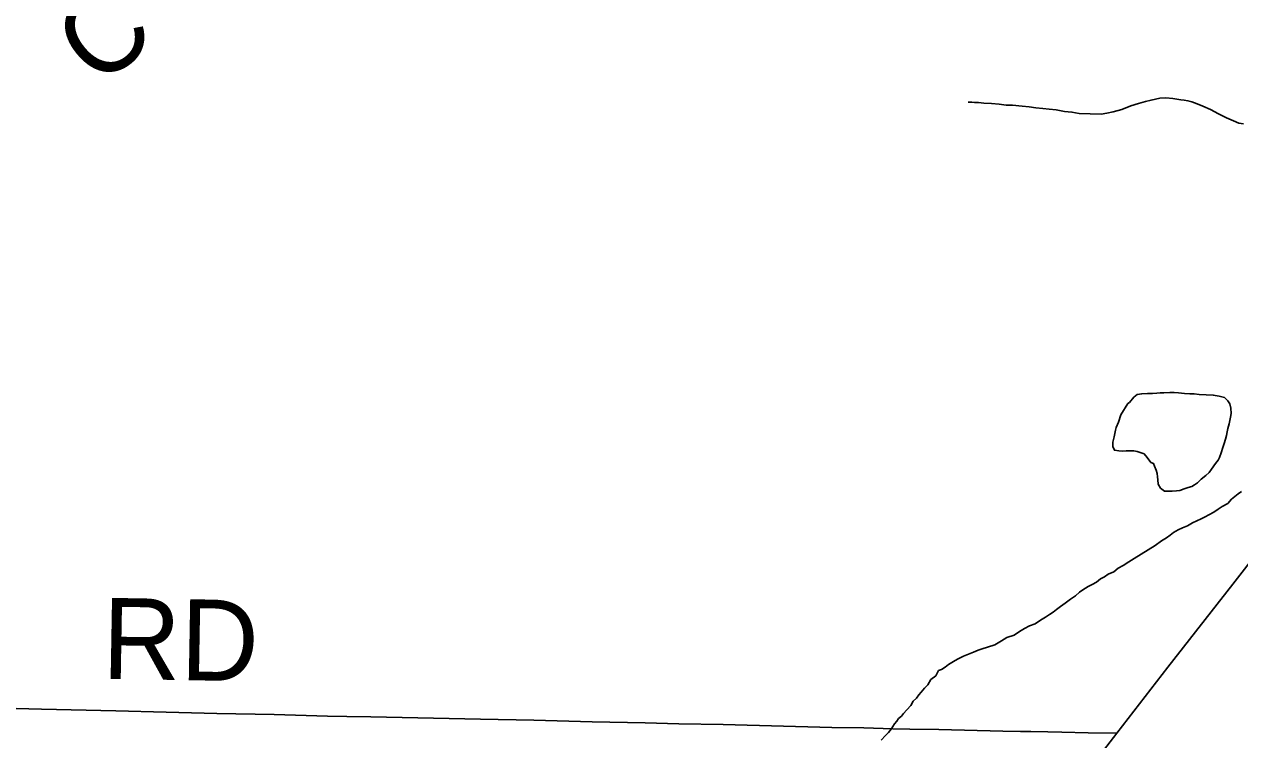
# Model space of a CAD drawing. Extents: x 0 to 34, y 0 to 22.
# Drawn here: x 24.806 to 25.659, y 15.392 to 15.894 of the extents above; entities that cross this region are included whole.
import ezdxf

# ---------------------------------------------------------------- set-up
doc = ezdxf.new("R2010")
doc.units = 0
for name, color, linetype in [('GM_X_County_Road_Text', 7, 'Continuous'), ('GM_X_Minor_Lake', 7, 'Continuous'), ('GM_X_Minor_River', 7, 'Continuous'), ('GM_X_State_Route', 7, 'Continuous'), ('GM_X_Township_Road', 7, 'Continuous'), ('GM_X_Township_Road_Text', 7, 'Continuous')]:
    doc.layers.add(name, color=color, linetype=linetype)

msp = doc.modelspace()

# ---------------------------------------------------------------- linework, layer by layer
at = {"layer": 'GM_X_Minor_Lake'}
for points in [[(25.58092, 15.62812), (25.5761, 15.62029), (25.57441, 15.61502), (25.57276, 15.61127), (25.57232, 15.60938), (25.57187, 15.60712), (25.57142, 15.60485), (25.57053, 15.60107), (25.57044, 15.59803), (25.57149, 15.59533), (25.57452, 15.59485), (25.57719, 15.59477), (25.57986, 15.59506), (25.58253, 15.59497), (25.58519, 15.59488), (25.58746, 15.59442), (25.59236, 15.59274), (25.59457, 15.59039), (25.59712, 15.58688), (25.599, 15.58606), (25.5997, 15.58413), (25.60075, 15.58143), (25.60144, 15.57913), (25.60175, 15.57683), (25.60206, 15.57454), (25.60234, 15.57148), (25.60378, 15.56877), (25.60676, 15.56677), (25.61209, 15.5666), (25.61514, 15.56688), (25.61744, 15.56718), (25.62052, 15.56822), (25.62322, 15.56927), (25.62591, 15.56995), (25.62784, 15.57102), (25.62979, 15.57248), (25.63254, 15.57506), (25.63567, 15.57761), (25.63803, 15.57982), (25.63962, 15.58205), (25.64242, 15.58614), (25.64439, 15.58836), (25.64521, 15.59023), (25.64646, 15.59362), (25.64773, 15.59738), (25.64857, 15.60002), (25.64943, 15.60303), (25.65028, 15.60567), (25.65074, 15.60831), (25.6512, 15.61058), (25.65207, 15.61398), (25.65252, 15.61625), (25.65297, 15.61852), (25.65344, 15.62116), (25.65318, 15.62498), (25.65251, 15.62804), (25.65105, 15.62999), (25.64884, 15.63235), (25.64507, 15.63323), (25.6409, 15.63413), (25.63596, 15.63429), (25.63101, 15.63446), (25.6276, 15.63495), (25.62456, 15.63505), (25.62075, 15.63518), (25.61658, 15.6357), (25.61353, 15.6358), (25.61049, 15.6359), (25.6063, 15.63566), (25.60363, 15.63574), (25.60134, 15.63544), (25.59828, 15.63516), (25.59486, 15.63527), (25.59066, 15.63503), (25.58759, 15.63437), (25.58525, 15.63255), (25.58208, 15.62884), (25.58092, 15.62812)], [(25.63803, 15.57982), (25.63962, 15.58205), (25.64242, 15.58614), (25.64439, 15.58836), (25.64521, 15.59023), (25.64646, 15.59362), (25.64773, 15.59738), (25.64857, 15.60002), (25.64943, 15.60303), (25.65028, 15.60567), (25.65074, 15.60831), (25.6512, 15.61058), (25.65207, 15.61398), (25.65252, 15.61625), (25.65297, 15.61852), (25.65344, 15.62116), (25.65318, 15.62498), (25.65251, 15.62804), (25.65105, 15.62999), (25.64884, 15.63235), (25.64507, 15.63323), (25.6409, 15.63413), (25.63596, 15.63429), (25.63101, 15.63446), (25.6276, 15.63495), (25.62456, 15.63505), (25.62075, 15.63518), (25.61658, 15.6357), (25.61353, 15.6358), (25.61049, 15.6359), (25.6063, 15.63566), (25.60363, 15.63574), (25.60134, 15.63544), (25.59828, 15.63516), (25.59486, 15.63527), (25.59066, 15.63503), (25.58759, 15.63437), (25.58525, 15.63255), (25.58208, 15.62884), (25.58092, 15.62812)], [(25.58092, 15.62812), (25.5761, 15.62029), (25.57441, 15.61502), (25.57276, 15.61127), (25.57232, 15.60938), (25.57187, 15.60712), (25.57142, 15.60485), (25.57053, 15.60107), (25.57044, 15.59803), (25.57149, 15.59533), (25.57452, 15.59485), (25.57719, 15.59477), (25.57986, 15.59506), (25.58253, 15.59497), (25.58519, 15.59488), (25.58746, 15.59442), (25.59236, 15.59274), (25.59457, 15.59039), (25.59712, 15.58688), (25.599, 15.58606), (25.5997, 15.58413), (25.60075, 15.58143), (25.60144, 15.57913), (25.60175, 15.57683), (25.60206, 15.57454), (25.60234, 15.57148), (25.60378, 15.56877), (25.60676, 15.56677), (25.61209, 15.5666), (25.61514, 15.56688), (25.61744, 15.56718), (25.62052, 15.56822), (25.62322, 15.56927), (25.62591, 15.56995), (25.62784, 15.57102), (25.62979, 15.57248), (25.63254, 15.57506), (25.63567, 15.57761), (25.63803, 15.57982)]]:
    msp.add_lwpolyline(points, dxfattribs=at)
at = {"layer": 'GM_X_Minor_River'}
for points in [[(25.66221, 15.82442), (25.6588, 15.82492), (25.65505, 15.82656), (25.65016, 15.82863), (25.64454, 15.83148), (25.63892, 15.83432), (25.63366, 15.83678), (25.62953, 15.83844), (25.62576, 15.8397), (25.62312, 15.84055), (25.62047, 15.84102), (25.61819, 15.8411), (25.6125, 15.84205), (25.60757, 15.84259), (25.60337, 15.84235), (25.60031, 15.84169), (25.59724, 15.84103), (25.5934, 15.84001), (25.5884, 15.83866), (25.58302, 15.83693), (25.57684, 15.83447), (25.5707, 15.83277), (25.56609, 15.83178), (25.56227, 15.83115), (25.54667, 15.83166), (25.54175, 15.83259), (25.53643, 15.83314), (25.53075, 15.83409), (25.52582, 15.83463), (25.52126, 15.83517), (25.51633, 15.83571), (25.51178, 15.83624), (25.50684, 15.83678), (25.5, 15.83739), (25.49544, 15.83754), (25.49051, 15.83808), (25.48519, 15.83864), (25.47987, 15.83881), (25.47607, 15.83932), (25.47341, 15.83941), (25.47151, 15.83947), (25.46923, 15.83955), (25.46885, 15.83956)], [(25.66083, 15.56651), (25.65849, 15.56469), (25.65615, 15.56286), (25.6538, 15.56104), (25.65104, 15.55808), (25.64716, 15.55593), (25.64444, 15.55412), (25.64133, 15.55194), (25.63784, 15.55015), (25.63513, 15.54872), (25.63242, 15.54728), (25.62932, 15.54587), (25.62623, 15.54445), (25.62274, 15.54228), (25.61926, 15.54087), (25.61617, 15.53945), (25.61307, 15.53765), (25.61072, 15.53583), (25.608, 15.53401), (25.6045, 15.53185), (25.60021, 15.52856), (25.58545, 15.51954), (25.58156, 15.51701), (25.57767, 15.51447), (25.57418, 15.51268), (25.57106, 15.51012), (25.56719, 15.50835), (25.56447, 15.50654), (25.56176, 15.5051), (25.55902, 15.50291), (25.55592, 15.50111), (25.55321, 15.49968), (25.55127, 15.4986), (25.54933, 15.49752), (25.54698, 15.4957), (25.54424, 15.49313), (25.54074, 15.49096), (25.53684, 15.48804), (25.53372, 15.48586), (25.53098, 15.48367), (25.52864, 15.48185), (25.52592, 15.48003), (25.52319, 15.47822), (25.5197, 15.47606), (25.51581, 15.47352), (25.51195, 15.47213), (25.50847, 15.47034), (25.50497, 15.46817), (25.50108, 15.46564), (25.49608, 15.4639), (25.4922, 15.46174), (25.48754, 15.45885), (25.48253, 15.45712), (25.47869, 15.4561), (25.47599, 15.45505), (25.47252, 15.45364), (25.46905, 15.45224), (25.46557, 15.45083), (25.46325, 15.44976), (25.46132, 15.44869), (25.4586, 15.44725), (25.45511, 15.44509), (25.45276, 15.44326), (25.45004, 15.44145), (25.44811, 15.44075), (25.44609, 15.43701), (25.44258, 15.43447), (25.44056, 15.43073), (25.4382, 15.42852), (25.43582, 15.42556), (25.43424, 15.42371), (25.43264, 15.42148), (25.43029, 15.41927), (25.42867, 15.41628), (25.42591, 15.41333), (25.42354, 15.41075), (25.42196, 15.4089), (25.42, 15.40706), (25.41879, 15.4052), (25.41721, 15.40334), (25.41481, 15.39962), (25.41283, 15.3974), (25.41086, 15.39519), (25.40771, 15.39187)]]:
    msp.add_lwpolyline(points, dxfattribs=at)
at = {"layer": 'GM_X_State_Route'}
for points in [[(25.57313, 15.39691), (25.60896, 15.44324), (25.65464, 15.50143), (25.692, 15.54957), (25.70849, 15.57059), (25.71659, 15.58157), (25.7215, 15.58872), (25.72606, 15.59607), (25.7311, 15.6053), (25.73479, 15.61311), (25.73734, 15.61941), (25.73956, 15.62581), (25.74175, 15.63353), (25.74395, 15.64381), (25.7462, 15.65726), (25.75078, 15.69114), (25.75665, 15.73489), (25.76276, 15.78237), (25.76637, 15.81075), (25.77336, 15.86), (25.77686, 15.88586), (25.78049, 15.91483)], [(25.55046, 15.36744), (25.57313, 15.39691)]]:
    msp.add_lwpolyline(points, dxfattribs=at)
at = {"layer": 'GM_X_Township_Road'}
msp.add_lwpolyline([(24.77361, 15.41489), (24.81829, 15.41373), (24.8705, 15.41246), (24.90593, 15.41167), (24.94135, 15.41068), (24.98176, 15.40988), (25.01905, 15.40892), (25.03273, 15.40869), (25.0495, 15.40832), (25.12658, 15.40666), (25.16388, 15.40604), (25.2049, 15.4049), (25.2422, 15.4041), (25.26582, 15.40354), (25.29689, 15.40292), (25.37325, 15.4009), (25.39561, 15.40054), (25.41607, 15.40004), (25.42787, 15.39973), (25.44837, 15.39944), (25.4931, 15.39828), (25.50551, 15.39809), (25.50799, 15.39808), (25.51292, 15.39801), (25.5247, 15.39777), (25.5346, 15.39754), (25.55321, 15.39719), (25.57313, 15.39691)], dxfattribs=at)

# ---------------------------------------------------------------- texts
at = {"layer": 'GM_X_County_Road_Text'}
msp.add_text('C', height=0.05682, rotation=39.34007, dxfattribs=at).set_placement((24.85829, 15.84885))
at = {"layer": 'GM_X_Township_Road_Text'}
msp.add_text('RD', height=0.056818, rotation=359.00866, dxfattribs=at).set_placement((24.86065, 15.43509))

doc.saveas('drawing.dxf')
